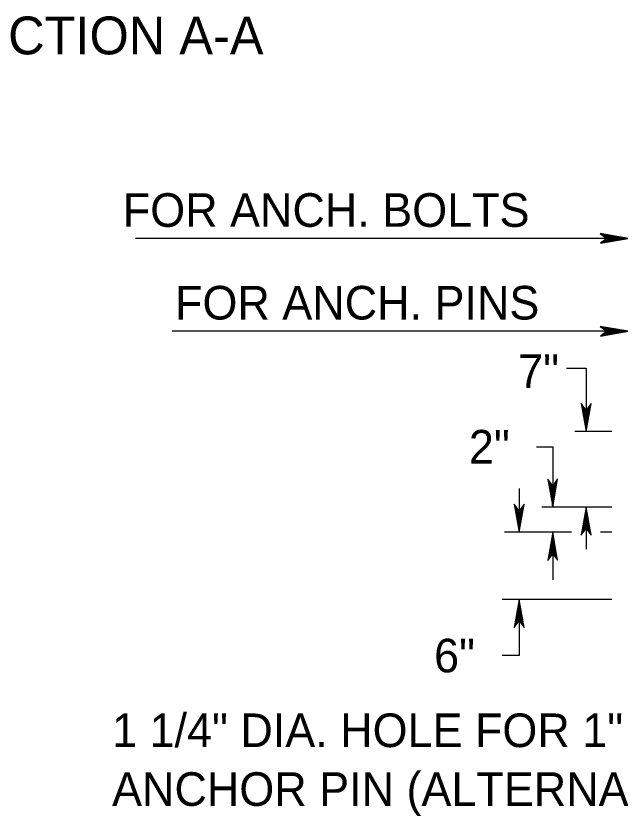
# Model space of a CAD drawing. Extents: x 499883 to 500983, y 499104 to 499764.
# Drawn here: x 500228.2 to 500300.2, y 499315.5 to 499410.7 of the extents above; entities that cross this region are included whole.
import ezdxf

# ---------------------------------------------------------------- set-up
doc = ezdxf.new("R2010")
doc.units = 0
for name, color, linetype in [('1', 7, 'Continuous'), ('24', 7, 'Continuous'), ('5', 7, 'Continuous')]:
    doc.layers.add(name, color=color, linetype=linetype)

msp = doc.modelspace()

# ---------------------------------------------------------------- linework, layer by layer
at = {"layer": '1'}
for p, q in [((500301.123, 499384.227), (500242.424, 499384.227)), ((500301.123, 499373.172), (500246.809, 499373.172))]:
    msp.add_line(p, q, dxfattribs=at)
at = {"layer": '24'}
for points in [[(500301.123, 499384.227), (500297.799, 499384.814), (500298.593, 499384.227), (500297.816, 499383.648), (500301.123, 499384.227)], [(500300.902, 499384.22), (500297.892, 499384.771), (500298.655, 499384.219), (500297.951, 499383.694), (500300.783, 499384.21)], [(500300.672, 499384.227), (500298.094, 499384.685), (500298.672, 499384.22), (500298.077, 499383.769), (500300.622, 499384.227)], [(500300.511, 499384.21), (500298.257, 499384.617), (500298.696, 499384.227), (500298.248, 499383.821), (500300.19, 499384.209), (500300.003, 499384.21), (500298.425, 499384.533), (500298.732, 499384.236), (500298.401, 499383.905), (500299.969, 499384.227), (500299.792, 499384.237), (500298.605, 499384.44), (500298.833, 499384.209), (500298.586, 499383.982), (500299.628, 499384.227), (500299.461, 499384.244), (500298.749, 499384.38), (500298.866, 499384.219), (500298.672, 499384.042), (500299.375, 499384.227), (500298.91, 499384.337), (500298.977, 499384.21), (500298.773, 499384.083), (500299.258, 499384.209), (500298.953, 499384.286), (500299.08, 499384.186), (500298.934, 499384.126), (500299.08, 499384.219), (500299.003, 499384.236)], [(500301.123, 499373.172), (500297.799, 499373.76), (500298.593, 499373.172), (500297.816, 499372.593), (500301.123, 499373.172)], [(500300.902, 499373.166), (500297.892, 499373.716), (500298.655, 499373.165), (500297.951, 499372.639), (500300.783, 499373.156)], [(500300.672, 499373.172), (500298.094, 499373.63), (500298.672, 499373.165), (500298.077, 499372.714), (500300.622, 499373.172)], [(500300.511, 499373.156), (500298.257, 499373.563), (500298.696, 499373.172), (500298.248, 499372.767), (500300.19, 499373.155), (500300.003, 499373.155), (500298.425, 499373.479), (500298.732, 499373.181), (500298.401, 499372.851), (500299.969, 499373.172), (500299.792, 499373.182), (500298.605, 499373.386), (500298.833, 499373.155), (500298.586, 499372.928), (500299.628, 499373.172), (500299.461, 499373.189), (500298.749, 499373.325), (500298.866, 499373.165), (500298.672, 499372.987), (500299.375, 499373.173), (500298.91, 499373.282), (500298.977, 499373.155), (500298.773, 499373.028), (500299.258, 499373.155), (500298.953, 499373.232), (500299.08, 499373.131), (500298.934, 499373.071), (500299.08, 499373.165), (500299.003, 499373.181)], [(500296.127, 499361.244), (500296.719, 499364.594), (500296.127, 499363.793), (500295.543, 499364.577), (500296.127, 499361.244), (500296.121, 499361.466), (500296.675, 499364.5), (500296.119, 499363.731), (500295.589, 499364.441), (500296.11, 499361.586), (500296.127, 499361.698), (500296.588, 499364.297), (500296.12, 499363.714), (500295.665, 499364.313), (500296.127, 499361.749), (500296.11, 499361.86), (500296.52, 499364.132), (500296.127, 499363.69), (500295.718, 499364.141), (500296.109, 499362.184), (500296.11, 499362.373), (500296.436, 499363.963), (500296.136, 499363.654), (500295.803, 499363.987), (500296.127, 499362.407), (500296.137, 499362.585), (500296.342, 499363.781), (500296.109, 499363.551), (500295.88, 499363.801), (500296.127, 499362.75), (500296.144, 499362.918), (500296.281, 499363.637), (500296.119, 499363.519), (500295.94, 499363.714), (500296.127, 499363.006), (500296.238, 499363.475), (500296.11, 499363.407), (500295.981, 499363.612), (500296.109, 499363.124), (500296.187, 499363.431), (500296.085, 499363.302), (500296.025, 499363.45), (500296.119, 499363.303), (500296.136, 499363.38)], [(500292.13, 499352.251), (500292.722, 499355.601), (500292.13, 499354.8), (500291.547, 499355.584), (500292.13, 499352.251), (500292.124, 499352.473), (500292.678, 499355.507), (500292.123, 499354.738), (500291.593, 499355.448), (500292.113, 499352.593), (500292.13, 499352.705), (500292.592, 499355.304), (500292.123, 499354.721), (500291.668, 499355.32), (500292.13, 499352.756), (500292.113, 499352.867), (500292.523, 499355.139), (500292.13, 499354.697), (500291.721, 499355.148), (500292.113, 499353.191), (500292.113, 499353.38), (500292.439, 499354.97), (500292.139, 499354.661), (500291.806, 499354.994), (500292.13, 499353.414), (500292.14, 499353.592), (500292.345, 499354.788), (500292.113, 499354.558), (500291.884, 499354.808), (500292.13, 499353.757), (500292.147, 499353.925), (500292.284, 499354.644), (500292.123, 499354.525), (500291.944, 499354.721), (500292.13, 499354.013), (500292.241, 499354.481), (500292.113, 499354.414), (500291.985, 499354.619), (500292.113, 499354.131), (500292.19, 499354.438), (500292.089, 499354.309), (500292.028, 499354.457), (500292.123, 499354.31), (500292.139, 499354.387)], [(500288.133, 499349.253), (500288.725, 499352.603), (500288.133, 499351.802), (500287.55, 499352.585), (500288.133, 499349.253), (500288.127, 499349.475), (500288.681, 499352.509), (500288.126, 499351.74), (500287.596, 499352.45), (500288.116, 499349.595), (500288.133, 499349.707), (500288.595, 499352.306), (500288.126, 499351.723), (500287.671, 499352.322), (500288.133, 499349.758), (500288.116, 499349.869), (500288.526, 499352.141), (500288.133, 499351.699), (500287.724, 499352.15), (500288.116, 499350.193), (500288.116, 499350.382), (500288.442, 499351.972), (500288.142, 499351.663), (500287.809, 499351.996), (500288.133, 499350.416), (500288.143, 499350.594), (500288.348, 499351.79), (500288.116, 499351.56), (500287.887, 499351.81), (500288.133, 499350.759), (500288.15, 499350.927), (500288.287, 499351.646), (500288.126, 499351.527), (500287.947, 499351.723), (500288.133, 499351.015), (500288.244, 499351.483), (500288.116, 499351.416), (500287.988, 499351.621), (500288.116, 499351.133), (500288.193, 499351.44), (500288.092, 499351.311), (500288.031, 499351.459), (500288.126, 499351.312), (500288.142, 499351.389)], [(500296.127, 499352.251), (500295.534, 499348.901), (500296.127, 499349.701), (500296.71, 499348.918), (500296.127, 499352.251), (500296.132, 499352.028), (500295.578, 499348.995), (500296.134, 499349.764), (500296.664, 499349.053), (500296.143, 499351.908), (500296.127, 499351.797), (500295.665, 499349.198), (500296.133, 499349.781), (500296.588, 499349.182), (500296.126, 499351.746), (500296.143, 499351.634), (500295.733, 499349.363), (500296.126, 499349.805), (500296.535, 499349.354), (500296.144, 499351.311), (500296.143, 499351.122), (500295.817, 499349.531), (500296.117, 499349.841), (500296.45, 499349.507), (500296.127, 499351.088), (500296.116, 499350.909), (500295.911, 499349.713), (500296.144, 499349.943), (500296.373, 499349.694), (500296.127, 499350.745), (500296.109, 499350.576), (500295.972, 499349.858), (500296.134, 499349.976), (500296.313, 499349.781), (500296.126, 499350.489), (500296.015, 499350.02), (500296.143, 499350.088), (500296.272, 499349.882), (500296.144, 499350.371), (500296.066, 499350.063), (500296.168, 499350.192), (500296.228, 499350.044), (500296.134, 499350.191), (500296.117, 499350.115)], [(500292.13, 499349.253), (500291.538, 499345.903), (500292.13, 499346.703), (500292.713, 499345.92), (500292.13, 499349.253), (500292.136, 499349.03), (500291.582, 499345.997), (500292.137, 499346.766), (500292.667, 499346.055), (500292.146, 499348.91), (500292.13, 499348.799), (500291.668, 499346.2), (500292.137, 499346.783), (500292.591, 499346.184), (500292.129, 499348.748), (500292.146, 499348.636), (500291.736, 499346.365), (500292.129, 499346.807), (500292.538, 499346.355), (500292.147, 499348.313), (500292.146, 499348.124), (500291.821, 499346.533), (500292.12, 499346.843), (500292.453, 499346.509), (500292.13, 499348.09), (500292.119, 499347.911), (500291.915, 499346.715), (500292.147, 499346.945), (500292.376, 499346.696), (500292.13, 499347.747), (500292.113, 499347.578), (500291.976, 499346.86), (500292.137, 499346.978), (500292.316, 499346.783), (500292.129, 499347.491), (500292.018, 499347.022), (500292.146, 499347.09), (500292.275, 499346.884), (500292.147, 499347.373), (500292.07, 499347.065), (500292.171, 499347.194), (500292.231, 499347.046), (500292.137, 499347.193), (500292.12, 499347.117)], [(500288.133, 499341.259), (500287.541, 499337.909), (500288.133, 499338.71), (500288.716, 499337.927), (500288.133, 499341.259), (500288.139, 499341.037), (500287.585, 499338.003), (500288.14, 499338.772), (500288.67, 499338.062), (500288.149, 499340.917), (500288.133, 499340.805), (500287.671, 499338.207), (500288.14, 499338.79), (500288.594, 499338.19), (500288.132, 499340.754), (500288.149, 499340.643), (500287.739, 499338.371), (500288.132, 499338.813), (500288.541, 499338.362), (500288.15, 499340.319), (500288.149, 499340.13), (500287.824, 499338.54), (500288.123, 499338.849), (500288.456, 499338.516), (500288.133, 499340.097), (500288.122, 499339.918), (500287.918, 499338.722), (500288.15, 499338.952), (500288.379, 499338.703), (500288.133, 499339.753), (500288.116, 499339.585), (500287.979, 499338.866), (500288.14, 499338.985), (500288.319, 499338.789), (500288.132, 499339.497), (500288.021, 499339.029), (500288.149, 499339.097), (500288.278, 499338.891), (500288.15, 499339.379), (500288.073, 499339.072), (500288.174, 499339.201), (500288.234, 499339.053), (500288.14, 499339.2), (500288.123, 499339.123)]]:
    msp.add_lwpolyline(points, dxfattribs=at)
at = {"layer": '5'}
for p, q in [((500299.179, 499361.244), (500294.789, 499361.244)), ((500288.133, 499354.463), (500288.133, 499349.253)), ((500299.179, 499352.251), (500290.856, 499352.251)), ((500296.127, 499352.251), (500296.127, 499347.254)), ((500294.39, 499349.253), (500286.41, 499349.253)), ((500292.13, 499349.253), (500292.13, 499343.604)), ((500299.179, 499349.253), (500297.811, 499349.253)), ((500299.179, 499341.259), (500286.134, 499341.259))]:
    msp.add_line(p, q, dxfattribs=at)
for points in [[(500293.781, 499368.79), (500296.127, 499368.79), (500296.127, 499361.244)], [(500290.202, 499359.433), (500292.13, 499359.433), (500292.13, 499352.251)], [(500288.133, 499341.259), (500288.133, 499334.582), (500286.114, 499334.582)]]:
    msp.add_lwpolyline(points, dxfattribs=at)

# ---------------------------------------------------------------- texts
for s, height, p in [('SECTION A-A', 4.5, (500219.241, 499406.135)), ('FOR ANCH. BOLTS', 4, (500240.929, 499385.609)), ('FOR ANCH. PINS', 4, (500247.15, 499374.578)), ('7"', 4, (500288.021, 499366.437)), ('2"', 4, (500282.154, 499357.433)), ('6"', 4, (500278.006, 499332.582)), ('1 1/4" DIA. HOLE FOR 1" DIA.', 4, (500239.652, 499323.689)), ('ANCHOR PIN (ALTERNATE SIDES)', 4, (500239.652, 499316.689))]:
    msp.add_text(s, height=height, dxfattribs=at).set_placement(p)

doc.saveas('drawing.dxf')
